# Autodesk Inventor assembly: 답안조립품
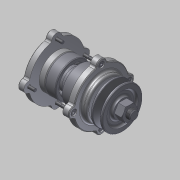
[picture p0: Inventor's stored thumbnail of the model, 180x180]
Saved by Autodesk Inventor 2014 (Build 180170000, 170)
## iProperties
Created: 2015-03
Part Number: 답안조립품
Document SubType Name: Assembly
Designer: MYHOME
Author: MYHOME
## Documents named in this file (11)
- C:\Documents and Settings\MYHOME\바탕 화면\450306V1016\답안조립품.iam
- C:\Documents and Settings\MYHOME\바탕 화면\450306V1016\본체.ipt
- C:\Documents and Settings\MYHOME\바탕 화면\450306V1016\커버.ipt
- C:\Documents and Settings\MYHOME\바탕 화면\450306V1016\커버2.ipt
- C:\Documents and Settings\MYHOME\바탕 화면\450306V1016\M 4 x 12.ipt
- C:\Documents and Settings\MYHOME\바탕 화면\450306V1016\축.ipt
- C:\Documents and Settings\MYHOME\바탕 화면\450306V1016\키(4 x 4 x 12).ipt
- C:\Documents and Settings\MYHOME\바탕 화면\450306V1016\V벨트풀리.ipt
- C:\Documents and Settings\MYHOME\바탕 화면\450306V1016\베어링 6204.ipt
- C:\Documents and Settings\MYHOME\바탕 화면\450306V1016\오일실.ipt
- C:\Documents and Settings\MYHOME\바탕 화면\450306V1016\너트 M12x1.25.ipt
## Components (14 placed, 6 different names)
1. KS B 1311 (I) 4 x 4 x 12:1
2. 그루브 풀리1:1
3. KS B 2023 6204 - 20 x 47 x 14:1 — 각도:1
4. KS B 2023 6204 - 20 x 47 x 14:2 — 각도:2
5. KS B 2804 D D - 20 32 8:1
6. KS B 1012 클래스 1 일반 - 미터 M12x1.25:1 — 각도:3
7. KS B 1003 - 미터 M 4 x 12:2
8. KS B 1003 - 미터 M 4 x 12:3
9. KS B 1003 - 미터 M 4 x 12:4
10. KS B 1003 - 미터 M 4 x 12:5
11. KS B 1003 - 미터 M 4 x 12:1
12. KS B 1003 - 미터 M 4 x 12:6
13. KS B 1003 - 미터 M 4 x 12:7
14. KS B 1003 - 미터 M 4 x 12:8
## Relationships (3: Angle 3)
- 각도:1 [Angle]: KS B 2023 6204 - 20 x 47 x 14:1
- 각도:2 [Angle]: KS B 2023 6204 - 20 x 47 x 14:2
- 각도:3 [Angle]: KS B 1012 클래스 1 일반 - 미터 M12x1.25:1
